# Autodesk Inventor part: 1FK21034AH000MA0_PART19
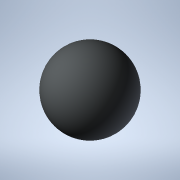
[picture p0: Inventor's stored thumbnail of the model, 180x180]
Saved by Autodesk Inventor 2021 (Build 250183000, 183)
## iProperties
Created: 2025-04
Part Number: 1FK21034AH000MA0_PART19
Material: Generic
Catalog Web Link: www.3dfindit.com
Description: -Servo synchronous motor
Document SubType Name: Modeling
Designer: psAdmin
Mass: 0.113097 g
Surface Area: 1.13097 cm^2
Volume: 0.113097 cm^3
Density: 1 g/cm^3
Appearance: PSOLRGB-212-217-219
Category: PARTsolutions
Title: 1FK21034AH000MA0_PART19
Author: Cadenas PARTsolutions
Comments: Servo synchronous motor
Sending System: PARTsolutions
Preprocessor: ST-DEVELOPER v19.3
PSOL_IDENT_0: {$CADENAS_DATA/23d-libs/siemens_ag/_cat_/ec/b7/1fk21034ah000ma0.prj},216 {VTYP=3D},{NB=1FK21034AH000
PSOL_IDENT_1: MA0_PART19},{LINA=1FK21034AH000MA0_PART19},{NN=1FK21034AH000MA0_PART19},{NOPRJ=TRUE},{DATE=19.08.202
PSOL_IDENT_2: 5 14:01:05},{GEOMDATE=30.07.2025 02:01:02},{VERSION=},{LINEID=10},{WBVAR=},{WBNUMERIC=}  {NB=1FK2103
PSOL_IDENT_3: 4AH000MA0_PART19},{LINA=1FK21034AH000MA0_PART19},{KT=DUMMY},{PREVIEW=../../../_pool_/7c/50/p_d211_xx
PSOL_IDENT_4: _00932j.png},{DESCSHORT=SIMOTICS S-1FK2 HD, SINAMICS S210 3AC 400V-480V, 1.01 Nm, 4500 rpm},{DESCLON
PSOL_IDENT_5: G=SIMOTICS S-1FK2 HD servo motor M0=1.27 Nm; PN = 0.48 kW at nN=4500 rpm (380-480 V); PN = 0.3 kW at
PSOL_IDENT_6: nN=2500 rpm (200-240 V); degree of protection IP64; cylindrical shaft D14 x 30 mm; absolute encoder
PSOL_IDENT_7: 22-bit + 12-bit multiturn (encoder AM22DQC); with OCC interface; plug size M17, rotatable; SIMOTICS
PSOL_IDENT_8: S-1FK2 servomotorfor a wide range of uses in industrial environments. SIMOTICS S‑1FK2 servomotors a
PSOL_IDENT_9: re compact synchronous motors with a high dynamic performance that set themselves apart as a result
PSOL_IDENT_10: of their high power density, degree of protection and overload capability. The motors are available
PSOL_IDENT_11: in two variants: as High Dynamic variant (highest dynamic performance as a result of the low intrins
PSOL_IDENT_12: ic moment of inertia for applications demanding a high dynamic performance with low moved masses) -
PSOL_IDENT_13: and as Compact variant (precise and stable closed-loop control for medium up to large moved masses a
PSOL_IDENT_14: s a result of a medium intrinsic moment of inertia). SIMOTICSS‑1FK2 servomotors fully exploit their
PSOL_IDENT_15: strengths in a system with the SINAMICSS210 frequency converter and simple connection using the one
PSOL_IDENT_16: cable connection (OCC). Advantages include the short control and positioning times, fast and precise
PSOL_IDENT_17: correction of disturbing quantities as well as stable control with a high dynamic performance. The
PSOL_IDENT_18: servo motors can be configured to address a wide range of requirements. For example with and without
PSOL_IDENT_19: holding brake, IP64 or IP65 degree of protection, singleturn or multiturn absolute encoders - to na
PSOL_IDENT_20: me just a few. Further, the servomotors are available in different shaft heights extending from 20 t
PSOL_IDENT_21: o 100. A shaft sealing ring is available to achieve an IP65 degree of protection and for subsequent
PSOL_IDENT_22: mounting at the motor or as spare part. SIMOTICS - the optimum motor for each and every motion contr
PSOL_IDENT_23: ol application.},{INTNO=4034106444822},{SUPPLIERALTNO=1FK2103-4AH00-0MA0},{MANUID=1FK21034AH000MA0},
PSOL_IDENT_24: {MANUNAME=Siemens},{MANUTYPEDESC=SYNCHRONOUS MOTOR 1FK2 HD 1,27 NM},{AAU732=SIMOTICS},{AAO057=S-1FK2
PSOL_IDENT_25: },{AAU734=SIMOTICS S-1FK2 HD servo motor M0=1.27 Nm; PN = 0.48 kW at nN=4500 rpm (380-480 V); PN = 0
PSOL_IDENT_26: .3 kW at nN=2500 rpm (200-240 V); degree of protection IP64; cylindrical shaft D14 x 30 mm; absolute
PSOL_IDENT_27: encoder 22-bit + 12-bit multiturn (encoder AM22DQC); with OCC interface; plug size M17, rotatable;}
PSOL_IDENT_28: ,{AAW338=SYNCHRONOUS MOTOR 1FK2 HD 1,27 NM},{AAO742=SIMOTICS},{AAO663=4034106444822},{NOCUPEROU=1},{
PSOL_IDENT_29: PRICEQUANTITY=1},{QUANTITYMIN=1},{QUANTITYINT=1},{CTN=85015100},{COO=RO},{AAO676=1FK2103-4AH00-0MA0}
PSOL_IDENT_30: ,{AAO677=Siemens AG},{ORDERUNIT=C62},{CONTENTUNIT=C62}
NB: 1FK21034AH000MA0_PART19
NT: Servo synchronous motor
NBSYN: $MANUID._PART19
LINA: 1FK21034AH000MA0_PART19
CATALOG: SIEMENS
PREVIEW: ../../../_pool_/7c/50/p_d211_xx_00932j.png
DESCSHORT: SIMOTICS S-1FK2 HD, SINAMICS S210 3AC 400V-480V, 1.01 Nm, 4500 rpm
DESCLONG: SIMOTICS S-1FK2 HD servo motor M0=1.27 Nm; PN = 0.48 kW at nN=4500 rpm (380-480 V); PN = 0.3 kW at nN=2500 rpm (200-240 V); degree of protection IP64; cylindric
INTNO: 4034106444822
SUPPLIERALTNO: 1FK2103-4AH00-0MA0
MANUID: 1FK21034AH000MA0
MANUNAME: Siemens
MANUTYPEDESC: SYNCHRONOUS MOTOR 1FK2 HD 1,27 NM
AAU732: SIMOTICS
AAO057: S-1FK2
AAU734: SIMOTICS S-1FK2 HD servo motor M0=1.27 Nm; PN = 0.48 kW at nN=4500 rpm (380-480 V); PN = 0.3 kW at nN=2500 rpm (200-240 V); degree of protection IP64; cylindric
AAW338: SYNCHRONOUS MOTOR 1FK2 HD 1,27 NM
AAO742: SIMOTICS
AAO663: 4034106444822.0
NOCUPEROU: 1
PRICEQUANTITY: 1
QUANTITYMIN: 1
QUANTITYINT: 1
CTN: 85015100
COO: RO
ARTICLENO: 1FK21034AH000MA0_PART19
BOMINFO: 1FK21034AH000MA0_PART19
CREATOR: CADENAS GmbH
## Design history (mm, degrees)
feature "2025_04_17_15_01_37_0314"
body "Solid1"
